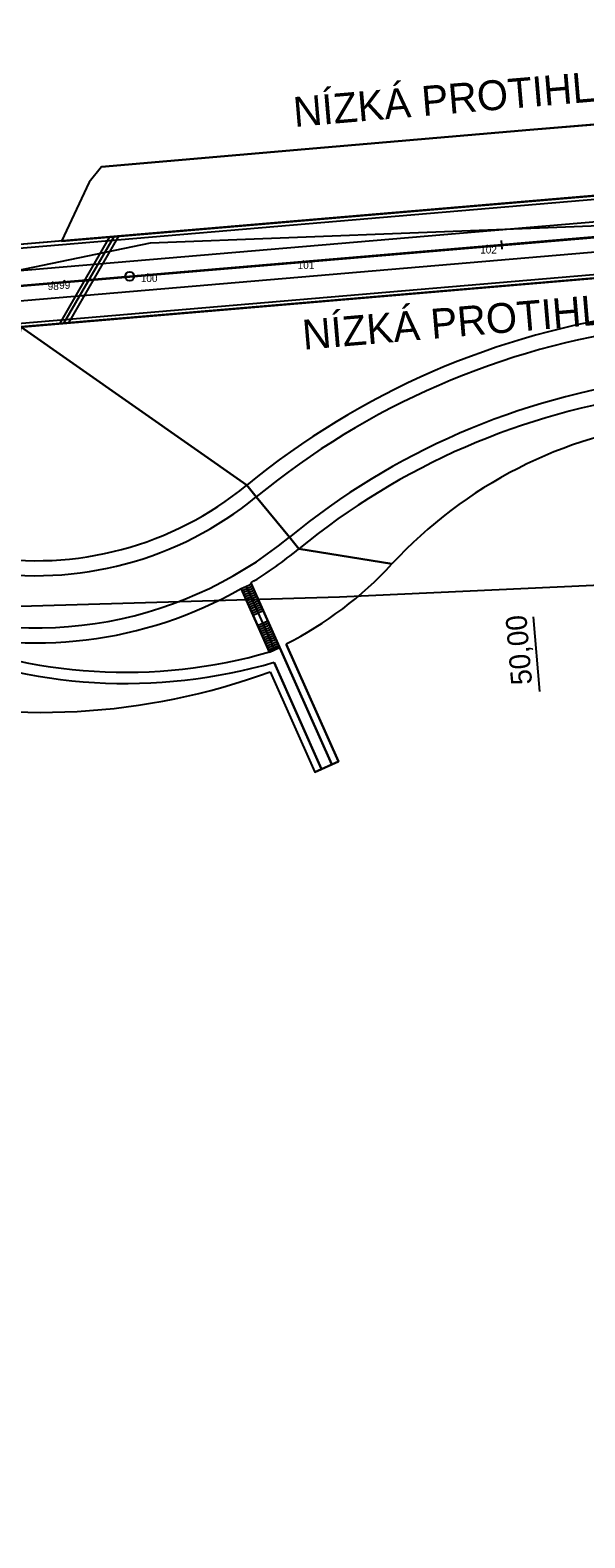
# Model space of a CAD drawing. Extents: x -606444 to -604546, y -1158114 to -1156869.
# Drawn here: x -605454.9 to -605380.6, y -1157300 to -1157098.2 of the extents above; entities that cross this region are included whole.
import ezdxf

# ---------------------------------------------------------------- set-up
doc = ezdxf.new("R2010")
doc.units = 0
for name, color, linetype in [('B_CHOD', 7, 'Continuous'), ('B_TRAM', 7, 'Continuous'), ('B_VOZ', 7, 'Continuous'), ('B_ZELEN', 7, 'Continuous'), ('geofyzikální profily_předběžný GTP', 7, 'Continuous'), ('NS_VB', 7, 'Continuous'), ('NS_VB_OBJ', 7, 'Continuous'), ('NS_VB_POP', 7, 'Continuous'), ('NS_VB_SVAHY', 7, 'Continuous'), ('OSA', 7, 'Continuous'), ('OSAPOP', 7, 'Continuous'), ('podélný profil trasou tramvaje', 7, 'Continuous')]:
    doc.layers.add(name, color=color, linetype=linetype)

msp = doc.modelspace()

# ---------------------------------------------------------------- linework, layer by layer
for p, q in [((-605393.71, -1157127.09), (-605393.81, -1157126.99)), ((-605393.71, -1157127.09), (-605393.81, -1157127.19)), ((-605393.71, -1157127.09), (-605393.61, -1157126.99)), ((-605393.71, -1157127.09), (-605393.61, -1157127.19)), ((-605418.26, -1157129.16), (-605418.36, -1157129.06)), ((-605418.26, -1157129.16), (-605418.36, -1157129.26)), ((-605418.26, -1157129.16), (-605418.16, -1157129.06)), ((-605418.26, -1157129.16), (-605418.16, -1157129.26)), ((-605451.8, -1157131.97), (-605451.9, -1157131.87)), ((-605451.8, -1157131.97), (-605451.9, -1157132.07)), ((-605451.8, -1157131.97), (-605451.7, -1157131.87)), ((-605451.8, -1157131.97), (-605451.7, -1157132.07)), ((-605450.27, -1157131.82), (-605450.37, -1157131.72)), ((-605450.27, -1157131.82), (-605450.37, -1157131.92)), ((-605450.27, -1157131.82), (-605450.17, -1157131.72)), ((-605450.27, -1157131.82), (-605450.17, -1157131.92)), ((-605439.1, -1157130.91), (-605439.2, -1157130.81)), ((-605439.1, -1157130.91), (-605439.2, -1157131.01)), ((-605439.1, -1157130.91), (-605439, -1157130.81)), ((-605439.1, -1157130.91), (-605439, -1157131.01))]:
    msp.add_line(p, q)
at = {"layer": 'B_CHOD'}
for points in [[(-605425.89, -1157159.11), (-605424.62, -1157160.66)], [(-605424.62, -1157160.66), (-605425.89, -1157159.11)], [(-605418.92, -1157167.61), (-605420.18, -1157166.07)], [(-605420.18, -1157166.07), (-605418.92, -1157167.61)], [(-605426.65, -1157172.93), (-605422.86, -1157181.43)], [(-605422.24, -1157182.81), (-605415.87, -1157197.1), (-605414.51, -1157196.49), (-605425.36, -1157172.18)]]:
    msp.add_lwpolyline(points, dxfattribs=at)
for centre, radius, start, end in [((-605358.98, -1157240.67), 105.5, 97.5799, 129.3665), ((-605358.98, -1157240.67), 103.5, 97.5799, 129.3665), ((-605358.98, -1157240.67), 96.5, 97.5799, 129.3665), ((-605358.98, -1157240.67), 94.5, 97.5799, 129.3665), ((-605454.12, -1157124.71), 46.5, 260.4921, 309.3665), ((-605454.12, -1157124.71), 44.5, 260.4921, 309.3665), ((-605454.12, -1157124.71), 53.5, 247.6491, 309.3665), ((-605454.12, -1157124.71), 55.5, 301.2049, 309.3665), ((-605454.12, -1157124.71), 55.5, 254.2844, 299.6622), ((-605442.1, -1157114.44), 69.69, 247.0406, 286.025), ((-605442.1, -1157114.44), 71.19, 247.0406, 286.1953)]:
    msp.add_arc(centre, radius, start, end, dxfattribs=at)
at = {"layer": 'B_TRAM'}
for p, q in [((-605374.61, -1157119.95), (-605477.91, -1157128.73)), ((-605476.98, -1157139.69), (-605373.68, -1157130.91))]:
    msp.add_line(p, q, dxfattribs=at)
at = {"layer": 'B_VOZ'}
for points in [[(-605424.62, -1157160.66), (-605420.18, -1157166.07)], [(-605420.18, -1157166.07), (-605424.62, -1157160.66)]]:
    msp.add_lwpolyline(points, dxfattribs=at)
for centre, radius, start, end in [((-605358.98, -1157240.67), 103.5, 97.5799, 129.3665), ((-605358.98, -1157240.67), 96.5, 97.5799, 129.3665), ((-605454.12, -1157124.71), 46.5, 260.4921, 309.3665), ((-605454.12, -1157124.71), 53.5, 247.6491, 309.3665)]:
    msp.add_arc(centre, radius, start, end, dxfattribs=at)
at = {"layer": 'B_ZELEN'}
for points in [[(-605450.71, -1157126.42), (-605374.61, -1157119.95), (-605373.01, -1157110.29), (-605388, -1157111.55), (-605418.1, -1157114.11), (-605445.35, -1157116.48), (-605446.98, -1157118.52), (-605450.71, -1157126.42)], [(-605373.68, -1157130.91), (-605456.14, -1157137.92), (-605425.89, -1157159.11)], [(-605425.89, -1157159.11), (-605456.14, -1157137.92), (-605460.31, -1157161.69), (-605461.47, -1157168.59)], [(-605418.92, -1157167.61), (-605406.46, -1157169.64)], [(-605406.46, -1157169.64), (-605418.92, -1157167.61)], [(-605422.86, -1157181.43), (-605426.65, -1157172.93)], [(-605425.36, -1157172.18), (-605414.51, -1157196.49), (-605413.6, -1157196.08), (-605420.62, -1157180.36)], [(-605422.78, -1157184.07), (-605416.78, -1157197.5), (-605415.87, -1157197.1), (-605422.24, -1157182.81)]]:
    msp.add_lwpolyline(points, dxfattribs=at)
for centre, radius, start, end in [((-605358.98, -1157240.67), 105.5, 97.5799, 129.3665), ((-605358.98, -1157240.67), 94.5, 97.5799, 129.3665), ((-605362.33, -1157210.3), 60, 96.6948, 137.3451), ((-605454.12, -1157124.71), 44.5, 260.4921, 309.3665), ((-605454.12, -1157124.71), 55.5, 301.2049, 309.3665), ((-605443.23, -1157135.76), 50, 296.8938, 317.3451), ((-605454.12, -1157124.71), 55.5, 254.2844, 299.6622), ((-605442.1, -1157114.44), 69.69, 247.0406, 286.025), ((-605442.1, -1157114.44), 71.19, 247.0406, 286.1953), ((-605453.43, -1157100.37), 89.14, 256.1067, 290.1169)]:
    msp.add_arc(centre, radius, start, end, dxfattribs=at)
at = {"layer": 'geofyzikální profily_předběžný GTP'}
for points in [[(-605670.78, -1157141.05), (-605656.02, -1157139.47), (-605613.88, -1157139.36), (-605584.8, -1157137.32), (-605531.41, -1157136.33), (-605491.56, -1157133.4), (-605482.07, -1157135.61), (-605438.78, -1157126.66), (-605383.23, -1157124.52), (-605352.34, -1157123.33), (-605321.95, -1157126), (-605284.14, -1157130.42), (-605243.3, -1157142.6), (-605207.83, -1157158.83), (-605179.98, -1157186.15), (-605165.29, -1157202.67), (-605149.23, -1157223.34), (-605135.07, -1157244.47), (-605115.92, -1157286.28), (-605103.22, -1157315.84), (-605095.33, -1157330.32), (-605036.97, -1157403.36), (-604999.08, -1157442.54), (-604970.8, -1157468.35)], [(-605668.89, -1157175.56), (-605638.05, -1157172.71), (-605616.09, -1157172.84), (-605512.92, -1157173.16), (-605468.49, -1157175.65), (-605413.5, -1157174.06), (-605313.44, -1157169.44), (-605274.57, -1157178.01), (-605221.39, -1157204.27), (-605178.57, -1157224), (-605160.32, -1157243.28), (-605143.64, -1157289.5), (-605117.17, -1157349.93), (-605096.21, -1157389.16), (-605065.9, -1157426.81), (-605053.52, -1157443.58), (-605045.82, -1157465.15), (-605020.21, -1157502.2)]]:
    msp.add_lwpolyline(points, dxfattribs=at)
at = {"layer": 'NS_VB'}
for p, q in [((-605388, -1157111.55), (-605373.01, -1157110.29)), ((-605418.1, -1157114.11), (-605388, -1157111.55)), ((-605445.35, -1157116.48), (-605418.1, -1157114.11)), ((-605445.35, -1157116.48), (-605446.98, -1157118.52)), ((-605446.98, -1157118.52), (-605450.71, -1157126.42)), ((-605444.27, -1157125.87), (-605450.98, -1157137.48)), ((-605443.05, -1157125.77), (-605449.77, -1157137.38)), ((-605426.65, -1157172.93), (-605422.86, -1157181.43)), ((-605425.36, -1157172.18), (-605414.51, -1157196.49)), ((-605420.62, -1157180.36), (-605413.6, -1157196.08)), ((-605422.24, -1157182.81), (-605415.87, -1157197.1)), ((-605422.78, -1157184.07), (-605416.78, -1157197.5)), ((-605413.6, -1157196.08), (-605416.78, -1157197.5))]:
    msp.add_line(p, q, dxfattribs=at)
for points in [[(-605374.61, -1157119.95), (-605477.91, -1157128.73)], [(-605476.98, -1157139.69), (-605373.68, -1157130.91)]]:
    msp.add_lwpolyline(points, dxfattribs=at)
for centre, radius, start, end in [((-605358.98, -1157240.67), 105.5, 97.5799, 129.3665), ((-605358.98, -1157240.67), 103.5, 97.5799, 129.3665), ((-605358.98, -1157240.67), 96.5, 97.5799, 129.3665), ((-605358.98, -1157240.67), 94.5, 97.5799, 129.3665), ((-605362.33, -1157210.3), 60, 96.6948, 137.3451), ((-605454.12, -1157124.71), 46.5, 260.4921, 309.3665), ((-605454.12, -1157124.71), 44.5, 260.4921, 309.3665), ((-605454.12, -1157124.71), 53.5, 247.6491, 309.3665), ((-605454.12, -1157124.71), 55.5, 301.2049, 309.3665), ((-605443.23, -1157135.76), 50, 296.8938, 317.3451), ((-605454.12, -1157124.71), 55.5, 254.2844, 299.6622), ((-605442.1, -1157114.44), 69.69, 247.0406, 286.025), ((-605442.1, -1157114.44), 71.19, 247.0406, 286.1953), ((-605453.43, -1157100.37), 89.14, 256.1067, 290.1169)]:
    msp.add_arc(centre, radius, start, end, dxfattribs=at)
at = {"layer": 'NS_VB_OBJ'}
for points in [[(-605374.57, -1157120.44), (-605477.87, -1157129.23)], [(-605450.37, -1157137.43), (-605443.66, -1157125.82)], [(-605477.02, -1157139.19), (-605373.72, -1157130.41)]]:
    msp.add_lwpolyline(points, dxfattribs=at)
at = {"layer": 'NS_VB_SVAHY'}
for p, q in [((-605426.65, -1157172.93), (-605425.3, -1157172.33)), ((-605426.53, -1157173.21), (-605425.17, -1157172.6)), ((-605426.41, -1157173.48), (-605425.05, -1157172.88)), ((-605425.97, -1157172.63), (-605422.18, -1157181.12)), ((-605426.29, -1157173.76), (-605424.93, -1157173.15)), ((-605426.16, -1157174.03), (-605424.81, -1157173.42)), ((-605426.04, -1157174.3), (-605424.68, -1157173.7)), ((-605425.92, -1157174.58), (-605424.56, -1157173.97)), ((-605425.8, -1157174.85), (-605424.44, -1157174.25)), ((-605425.67, -1157175.12), (-605424.32, -1157174.52)), ((-605425.55, -1157175.4), (-605424.2, -1157174.79)), ((-605425.43, -1157175.67), (-605424.07, -1157175.07)), ((-605425.31, -1157175.95), (-605423.95, -1157175.34)), ((-605425.18, -1157176.22), (-605423.83, -1157175.62)), ((-605425.06, -1157176.49), (-605423.71, -1157175.89)), ((-605424.45, -1157177.86), (-605423.09, -1157177.26)), ((-605424.33, -1157178.14), (-605422.97, -1157177.53)), ((-605424.21, -1157178.41), (-605422.85, -1157177.81)), ((-605424.08, -1157178.69), (-605422.73, -1157178.08)), ((-605423.96, -1157178.96), (-605422.61, -1157178.35)), ((-605423.84, -1157179.23), (-605422.48, -1157178.63)), ((-605423.72, -1157179.51), (-605422.36, -1157178.9)), ((-605423.59, -1157179.78), (-605422.24, -1157179.18)), ((-605423.47, -1157180.06), (-605422.12, -1157179.45)), ((-605423.35, -1157180.33), (-605421.99, -1157179.72)), ((-605423.23, -1157180.6), (-605421.87, -1157180)), ((-605423.11, -1157180.88), (-605421.75, -1157180.27)), ((-605422.98, -1157181.15), (-605421.63, -1157180.55)), ((-605422.86, -1157181.43), (-605421.51, -1157180.82)), ((-605421.51, -1157180.82), (-605422.85, -1157181.42))]:
    msp.add_line(p, q, dxfattribs=at)
at = {"layer": 'OSA'}
msp.add_line((-605374.15, -1157125.43), (-605584.3, -1157143.3), dxfattribs=at)
for points in [[(-605374.32, -1157123.43), (-605584.46, -1157141.31)], [(-605584.13, -1157145.29), (-605373.98, -1157127.42)]]:
    msp.add_lwpolyline(points, dxfattribs=at)
at = {"layer": 'OSAPOP'}
for p, q in [((-605391.7, -1157127.52), (-605391.8, -1157126.33)), ((-605386.67, -1157186.71), (-605387.51, -1157176.74))]:
    msp.add_line(p, q, dxfattribs=at)
msp.add_circle((-605441.57, -1157131.16), 0.6, dxfattribs=at)
at = {"layer": 'podélný profil trasou tramvaje'}
msp.add_lwpolyline([(-605358.23, -1157124.22), (-605590.31, -1157143.82), (-605624.54, -1157148.59), (-605648.21, -1157155.58), (-605668.25, -1157164.47)], dxfattribs=at)

# ---------------------------------------------------------------- texts
for s, p in [('102', (-605394.65, -1157128.09)), ('101', (-605419.08, -1157130.16)), ('98', (-605452.54, -1157132.97)), ('99', (-605451.01, -1157132.82)), ('100', (-605440.08, -1157131.91))]:
    msp.add_text(s, height=1).set_placement(p)
at = {"layer": 'NS_VB_POP'}
for s, p in [('NÍZKÁ PROTIHLUKOVÁ STĚNA DL. 190,00 m', (-605419.5, -1157111.16)), ('NÍZKÁ PROTIHLUKOVÁ STĚNA DL. 160,00 m', (-605418.29, -1157140.98))]:
    msp.add_text(s, height=4, rotation=4.8613, dxfattribs=at).set_placement(p)
at = {"layer": 'OSAPOP'}
msp.add_text('50,00', height=2.8, rotation=94.8613, dxfattribs=at).set_placement((-605387.69, -1157185.71))

doc.saveas('drawing.dxf')
